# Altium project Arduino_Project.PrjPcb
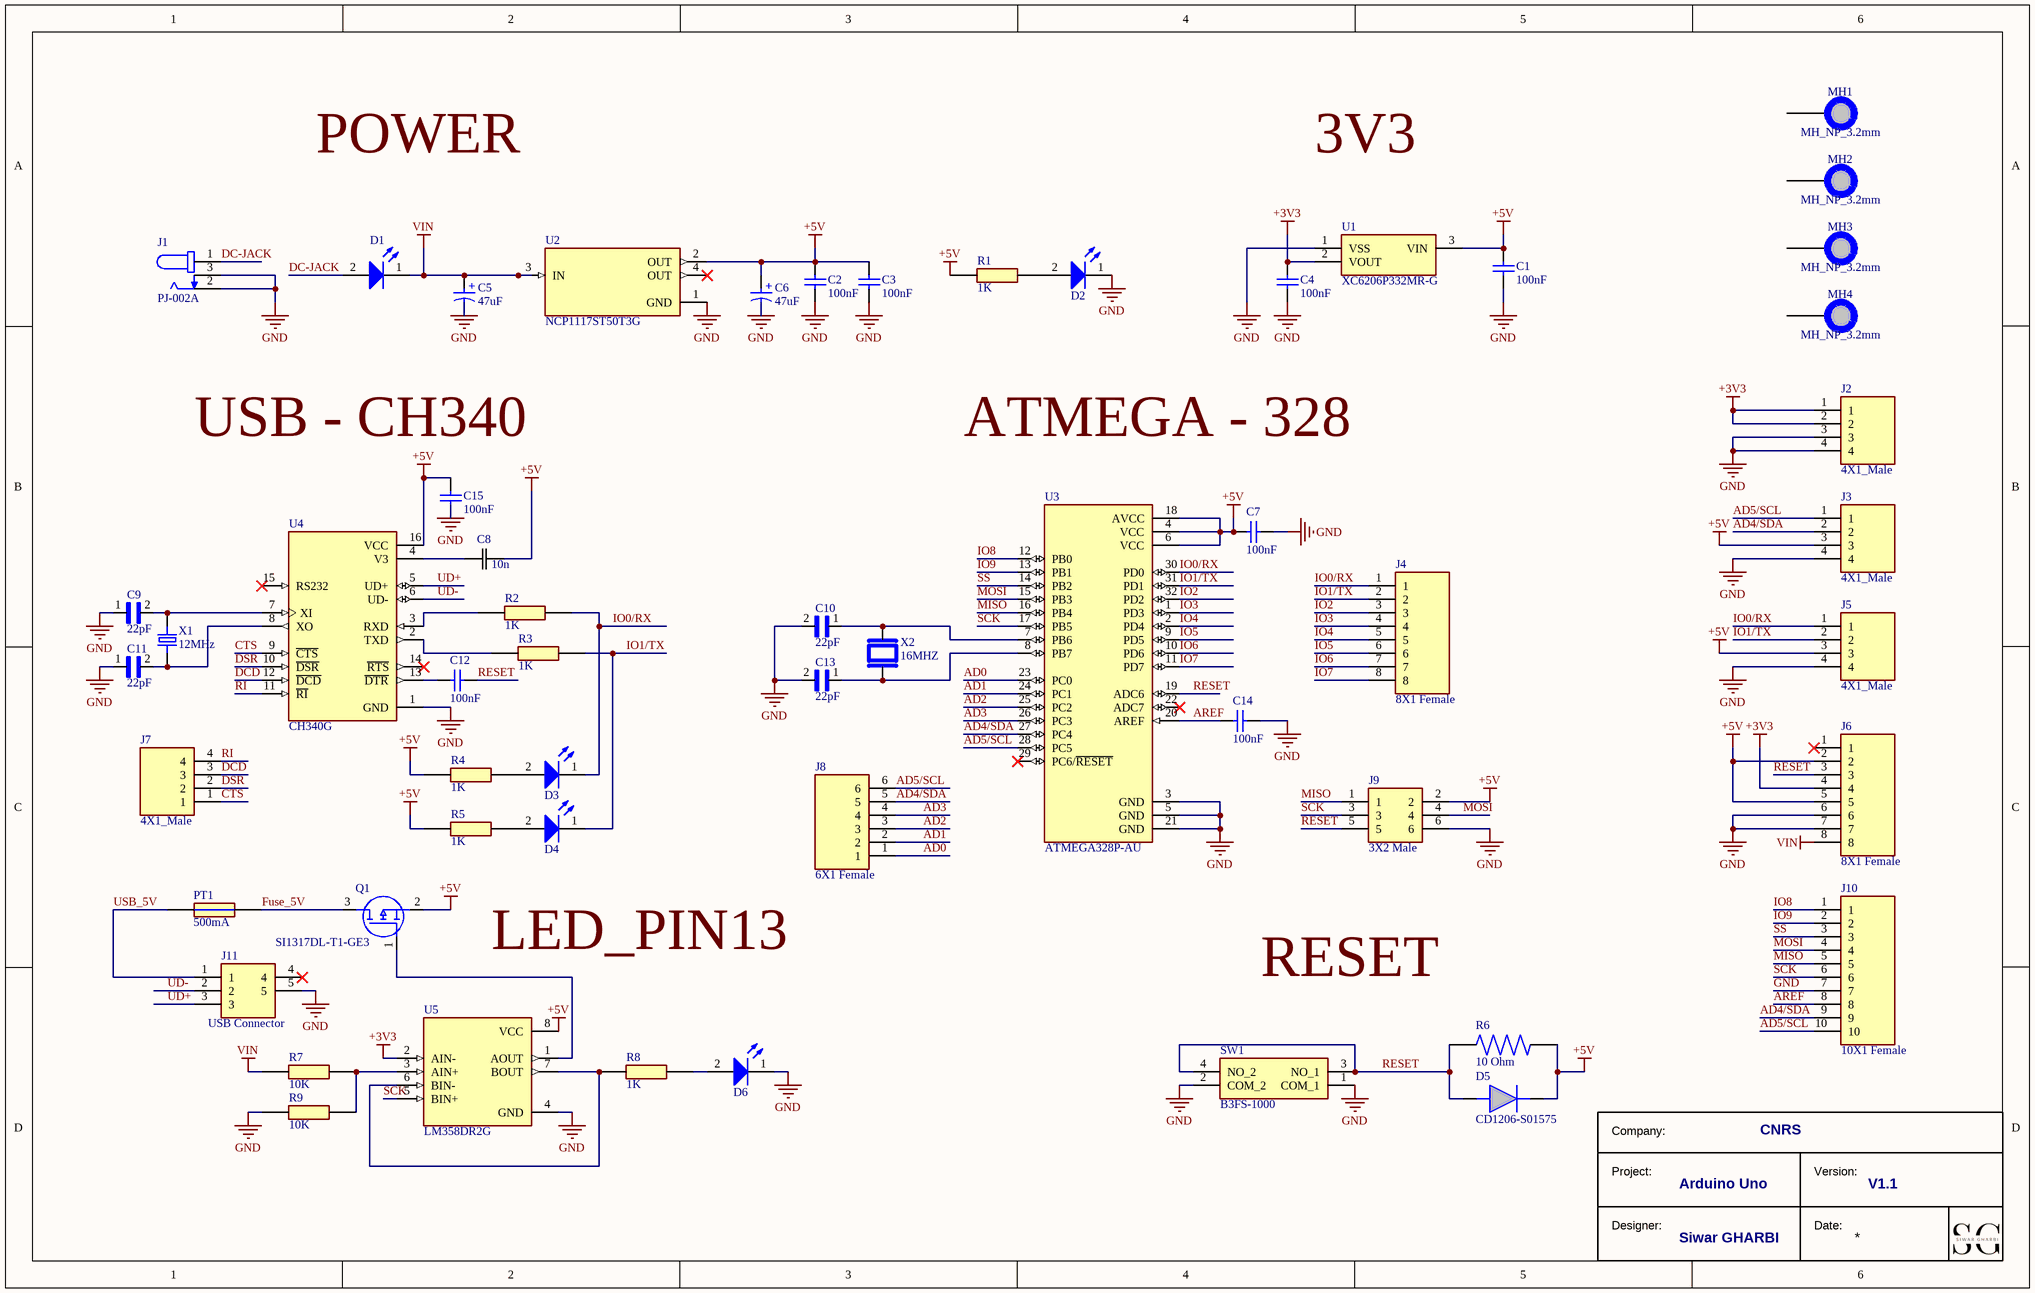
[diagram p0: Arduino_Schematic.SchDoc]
Company: CNRS; Project: Arduino Uno; ProjectDesigner: Siwar GHARBI; ProjectVersion: V1.1
1 sheet, 56 parts. Net scope: global (net labels, ports and power ports of the same name join across sheets).
Board file: Arduino_PCB.PcbDoc

## Sheet Arduino_Schematic.SchDoc
size 381 x 241 mm; SheetNumber: 1; SheetTotal: 1

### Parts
?  TittleBlock  (value not drawn)  (graphical)
C1  100nF  [WCAP-CSGP_0603_L1.6W0.8H0.8_Wave]
C2  100nF  [WCAP-CSGP_0603_L1.6W0.8H0.8_Wave]
C3  100nF  [WCAP-CSGP_0603_L1.6W0.8H0.8_Wave]
C4  100nF  [WCAP-CSGP_0603_L1.6W0.8H0.8_Wave]
C5  47uF  [WCAP-ASLI_D6.3H7.7]
C6  47uF  [WCAP-ASLI_D6.3H7.7]
C7  100nF  [WCAP-CSGP_0603_L1.6W0.8H0.8_Wave]
C8  10n  [CAP_C0805_VEN-M]
C9  22pF  [CAPC2012X140N]
C10  22pF  [CAPC2012X140N]
C11  22pF  [CAPC2012X140N]
C12  100nF  [WCAP-CSGP_0603_L1.6W0.8H0.8_Wave]
C13  22pF  [CAPC2012X140N]
C14  100nF  [WCAP-CSGP_0603_L1.6W0.8H0.8_Wave]
C15  100nF  [WCAP-CSGP_0603_L1.6W0.8H0.8_Wave]
D1  Infrared, 1.4V, 140°  [WL-SICW_0805_L2W1.3H0.8]  (value not drawn)
D2  Green LED  [LEDC2012X80N]  (value not drawn)
D3  Green LED  [LEDC2012X80N]  (value not drawn)
D4  Green LED  [LEDC2012X80N]  (value not drawn)
D5  CD1206-S01575  [DIOC3215X95N]
D6  Green LED  [LEDC2012X80N]  (value not drawn)
J1  PJ-002A  [CUI_PJ-002A]
J2  4X1_Male  [HDRV4W95P0X254_1X4_1016X254X854P]
J3  4X1_Male  [HDRV4W95P0X254_1X4_1016X254X854P]
J4  8X1 Female  [RHDR8W80P0X254_1X8_2082X254X850P]
J5  4X1_Male  [HDRV4W95P0X254_1X4_1016X254X854P]
J6  8X1 Female  [RHDR8W80P0X254_1X8_2082X254X850P]
J7  4X1_Male  [HDRV4W95P0X254_1X4_1016X254X854P]
J8  6X1 Female  [RHDR6W80P0X254_1X6_1574X254X870P]
J9  3X2 Male  [HDRV6W67P254_2X3_762X483X858P]
J10  10X1 Female  [RHDR10W80P0X254_1X10_2590X254X850P]
J11  USB Connector  [1734035-2USB]
MH1  MH_NP_3.2mm  [MH_NP_3.2mm]  (no BOM)
MH2  MH_NP_3.2mm  [MH_NP_3.2mm]  (no BOM)
MH3  MH_NP_3.2mm  [MH_NP_3.2mm]  (no BOM)
MH4  MH_NP_3.2mm  [MH_NP_3.2mm]  (no BOM)
PT1  500mA  [0ZCK0050AF2E]
Q1  SI1317DL-T1-GE3  [SOT65P210X110-3N]
R1  1K  [RESC2012X60N]
R2  1K  [RESC2012X60N]
R3  1K  [RESC2012X60N]
R4  1K  [RESC2012X60N]
R5  1K  [RESC2012X60N]
R6  10 Ohm  [RESC3216X70N]
R7  10K  [RESC2012X60N]
R8  1K  [RESC2012X60N]
R9  10K  [RESC2012X60N]
SW1  B3FS-1000  [B3FS1000]
U1  XC6206P332MR-G  [SOT95P280X130-3N]
U2  NCP1117ST50T3G  [SOT230P700X180-4N]
U3  ATMEGA328P-AU  [QFP80P900X900X120-32N]
U4  CH340G  [SOIC127P600X180-16N]
U5  LM358DR2G  [SOIC127P600X175-8N]
X1  12MHz  [XTAL_ECS-120-S-5PX-TR]
X2  16MHZ  [XTAL_ABLS-9.216MHZ-B4-T]

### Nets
+3V3: C4.2 J2.1 J2.2 J6.4 U1.2(VOUT) U5.2(AIN-)
+5V: C1.2 C2.2 C3.1 C6.1(P) C7.1 C8.2 C15.2 D5.1(K) J3.3 J5.3 J6.2 J6.5 J9.2 Q1.2(S) R1.1 R4.1 R5.1 R6.2 U1.3(VIN) U2.2(OUT) U3.4(VCC) U3.6(VCC) U3.18(AVCC) U4.16(VCC) U5.8(VCC)
GND: C1.1 C2.1 C3.2 C4.1 C5.2(N) C6.2(N) C7.2 C9.1 C10.2 C11.1 C13.2 C14.2 C15.1 D2.1(K) D6.1(K) J1.2 J1.3 J2.3 J2.4 J3.4 J5.4 J6.6 J6.7 J9.6 J10.7 J11.5 R9.1 SW1.1(COM_1) SW1.2(COM_2) U1.1(VSS) U2.1(GND) U3.3(GND) U3.5(GND) U3.21(GND) U4.1(GND) U5.4(GND)
VIN: C5.1(P) D1.1(K) J6.8 R7.1 U2.3(IN)
AD0: J8.1 U3.23(PC0)
AD1: J8.2 U3.24(PC1)
AD2: J8.3 U3.25(PC2)
AD3: J8.4 U3.26(PC3)
AD4/SDA: J3.2 J8.5 J10.9 U3.27(PC4)
AD5/SCL: J3.1 J8.6 J10.10 U3.28(PC5)
AREF: C14.1 J10.8 U3.20(AREF)
CTS: J7.1 U4.9(~{CTS})
DC-JACK: D1.2(A) J1.1
DCD: J7.3 U4.12(~{DCD})
DSR: J7.2 U4.10(~{DSR})
Fuse_5V: PT1.2 Q1.3(D)
IO0/RX: D3.1(K) J4.1 J5.1 R2.2 U3.30(PD0)
IO1/TX: D4.1(K) J4.2 J5.2 R3.2 U3.31(PD1)
IO2: J4.3 U3.32(PD2)
IO3: J4.4 U3.1(PD3)
IO4: J4.5 U3.2(PD4)
IO5: J4.6 U3.9(PD5)
IO6: J4.7 U3.10(PD6)
IO7: J4.8 U3.11(PD7)
IO8: J10.1 U3.12(PB0)
IO9: J10.2 U3.13(PB1)
MISO: J9.1 J10.5 U3.16(PB4)
MOSI: J9.4 J10.4 U3.15(PB3)
RESET: C12.2 D5.2(A) J6.3 J9.5 R6.1 SW1.3(NO_1) SW1.4(NO_2) U3.19(ADC6)
RI: J7.4 U4.11(~{RI})
SCK: J9.3 J10.6 U3.17(PB5) U5.5(BIN+)
SS: J10.3 U3.14(PB2)
UD+: J11.3 U4.5(UD+)
UD-: J11.2 U4.6(UD-)
USB_5V: J11.1 PT1.1
NetC8_1: C8.1 U4.4(V3)
NetC9_2: C9.2 U4.7(XI) X1.1
NetC10_1: C10.1 U3.7(PB6) X2.1
NetC11_2: C11.2 U4.8(XO) X1.2
NetC12_1: C12.1 U4.13(~{DTR})
NetC13_1: C13.1 U3.8(PB7) X2.2
NetD2_2: D2.2(A) R1.2
NetD3_2: D3.2(A) R4.2
NetD4_2: D4.2(A) R5.2
NetD6_2: D6.2(A) R8.2
NetQ1_1: Q1.1(G) U5.1(AOUT)
NetR2_1: R2.1 U4.3(RXD)
NetR3_1: R3.1 U4.2(TXD)
NetR7_2: R7.2 R9.2 U5.3(AIN+)
NetR8_1: R8.1 U5.6(BIN-) U5.7(BOUT)

Not connected (* = marked no-connect by the designer): J6 1*; J11 4*; MH1 1; MH2 1; MH3 1; MH4 1; U2 4(OUT)*; U3 22(ADC7)* 29(PC6/~{RESET})*; U4 14(~{RTS})* 15(RS232)*

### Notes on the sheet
- POWER
- 3V3
- (near C15) USB - CH340
- ATMEGA - 328
- LED_PIN13
- RESET

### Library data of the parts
C1-C4 C7 C12 C14 C15 = Capacitor 885012206071R: WCAP-CSGP Multilayer Ceramic Chip Capacitor, General Purpose, size 0603, X7R, 100nF, 25VDC; Manufacturer: Wurth Elektronik; Case/Size Code: 0603; Capacitance Tolerance: +/-10%; Dissipation Factor: 3.5%; Insulation Resistance: 5GOhm; Rated Voltage (DC): 25V; Technical Reference: X7R0603104K025DFCT20000
C5 C6 = Capacitor 865080443007: WCAP-ASLI Aluminum Electrolytic Capacitor, V-Chip, D6.3 x H5.5mm, 47uF, 25V; Manufacturer: Wurth Elektronik; Capacitance Tolerance: +/-20%; Dissipation Factor: 14%; Endurance: 2000h; Leakage Current: 11.75uA; Ripple Current: 220mA; Technical Reference: ASED055470M025DVCTBB000
C8 = Cap 0805X7R500-104KNE: 0.1 µF ±10% 50V Ceramic Capacitor X7R 0805 (2012 Metric); Mfr_Name: Venkel
C9-C11 C13 = C0805C220J5GACTU: 22pF Â±5% 50V Ceramic Capacitor C0G, NP0 0805 _2012 Metric_; MF: KEMET
D1 = 15408085BA400: WL-SICW SMT Chip LED Infrared Waterclear, size 0805, Infrared, 1.4V, 140°; Manufacturer: Wurth Elektronik; Case/Size Code: 0805; Centroid Wavelength: 845nm; Chip Technology: AlGaAs; Forward Voltage Max: 2V; Peak Wavelength: 850nm; Radiant Intensity: 1.5mW/sr; Radiant Intensity Min: 0.6mW/sr
D2-D4 D6 = LED Green _R971-KN-1: Standard LEDs - SMD Green, 570nm 26mcd, 20mA; Manufacturer_Name: ams OSRAM; Manufacturer_Part_Number: LG R971-KN-1; Geometry.Height: 0.8mm
D5 = CD1206-S01575: Diode Switching 100V 0.15A 4ns SMD1206 Bourns CD1206-S01575 Switching Diode, 150mA, 100V, 4ns, 2-Pin 1206; Geometry.Height: 0.95mm
J1 = PJ-002A: 2.0 x 6.5 mm, 2.5 A, Horizontal, Through Hole, Dc Power Jack Connector; MF: CUI Devices
J2 J3 J5 J7 = Con 4X1 61300411121: WR-PHD 2.54mm Pin Header THT Straight 4p Wurth Elektronik WR-PHD Series, Series Number 6130, 2.54mm Pitch 4 Way 1 Row Straight PCB Header, Solder Termination; Geometry.Height: 8.54mm
J4 J6 = Con 8X1 PPTC081LFBN-RC: Connector; Manufacturer_Name: Sullins
J8 = Con 6X1 PPTC061LFBN-RC: Connector; Manufacturer_Name: Sullins
J9 = Con 3X2 67997-206HLF: Connector; Manufacturer_Name: Amphenol
J10 = Con 10X1 PPTC101LFBN-RC: 10 Position Header Connector 0.100" (2.54mm) Through Hole Tin; Manufacturer_Name: Sullins
J11 = Con USB 1734035-4: Conn Mini USB 2.0 Type B RCP 5 POS 0.8mm Solder RA SMD 5 Terminal 1 Port Automotive T/R; Manufacturer_Name: TE Connectivity
MH1-MH4 = MH_NP_3.2mm: Mounting Hole 3.2mm
PT1 = PT 0ZCK0050AF2E: PTC Resettable Fuse 0.5A(hold) 1A(trip) 9VDC 100A 0.5W 0.1s 0.15Ohm SMD Solder Pad 0805 2.3 X 1.5 X 0.9mm Automotive; Manufacturer_Name: Bel
Q1 = SI1317DL-T1-GE3: Vishay SI1317DL-T1-GE3 P-channel MOSFET Transistor, 1.1 A, -20 V, 3-Pin SOT-323; Geometry.Height: 1.1mm
R1-R5 R8 = Res RC0805FR-071KL: YAGEO - RC0805FR-071KL - SMD Chip Resistor, 1 kohm, +/- 1%, 125 mW, 0805 [2012 Metric], Thick Film, General Purpose; Geometry.Height: 0.6mm
R6 = Res FCR1206J10R: Res 1206 10 Ohm 5% 1/8W Â±500ppm/Â°C Molded SMD SMD T/R; Resistance: 10; Power_Rating: .125 W; MF: TE Connectivity
R7 R9 = Res RC0805FR-0710KL: YAGEO - RC0805FR-0710KL - SMD Chip Resistor, 10 kohm, +/- 1%, 125 mW, 0805 [2012 Metric], Thick Film, General Purpose; Geometry.Height: 0.6mm
SW1 = Switch: Switch Tactile N.O. SPST Flat Plunger Gull Wing 0.05A 24VDC 0.98N SMD Bag; Manufacturer_Name: Omron Electronics; Geometry.Height: 3.3mm
U1 = Voltage Regulators: LDO Voltage Regulators 1uA Low Quiescent 3 Terminal, Low ESR Cap. Compatible, Voltage Regulator; Manufacturer_Name: Torex; Geometry.Height: 1.3mm
U2 = Voltage Regulator NCP1117ST50T3G: Linear Voltage Regulator IC 1 Output 1A SOT-223; MF: ON Semiconductor
U3 = ATMEGA328P-AU: AVR AVRÂ® ATmega Microcontroller IC 8-Bit 20MHz 32KB (16K x 16) FLASH 32-TQFP (7x7); MF: Microchip Technology
U4 = CH340G: USB Interface Integrated Circuit; MF: WCH
U5 = AOP LM358DR2G: General Purpose Amplifier 2 Circuit - 8-SOIC; MF: ON Semiconductor
X1 = Crystal 12MHz - ECS-120-S-5PX-TR: 12MHz Â±30ppm Crystal Series 50 Ohms HC-49/US; MF: ECS Inc.
X2 = ABLS-9.216MHZ-B4-T: HC/49US (AT49) SMD LOW PROFILE CRYSTAL; MF: Abracon LLC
